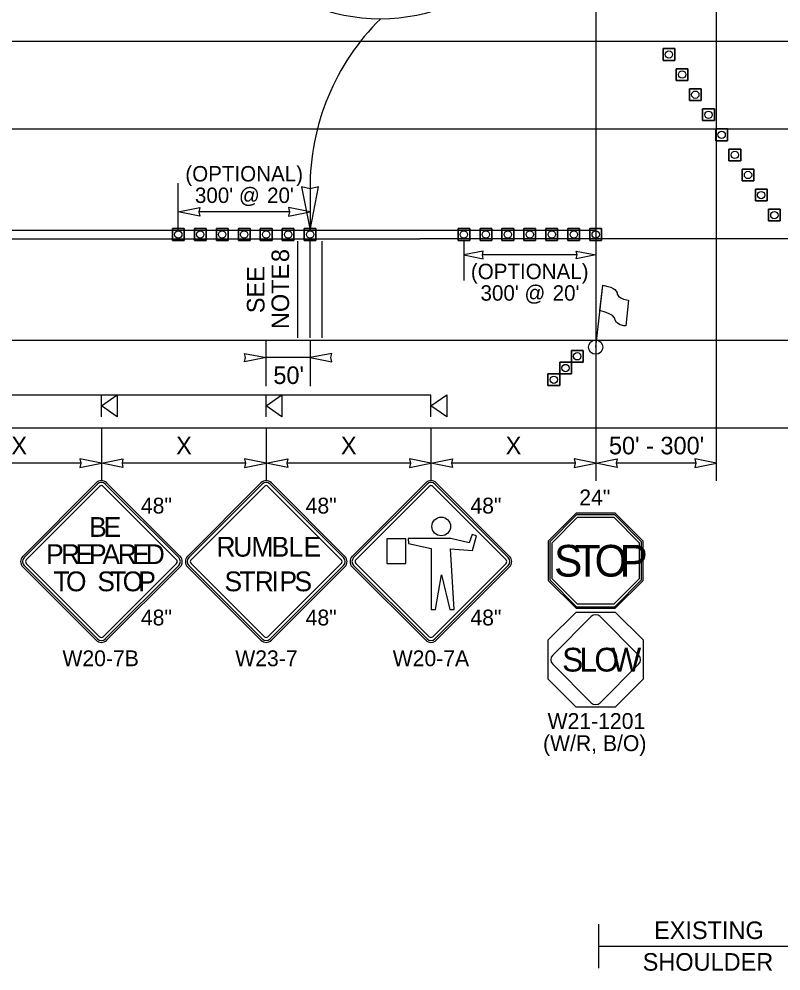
# Model space of a CAD drawing. Extents: x 99999.1 to 100095.7, y 99995 to 100010.7.
# Drawn here: x 100001.652 to 100005.12, y 100003.262 to 100007.592 of the extents above; entities that cross this region are included whole.
import ezdxf

# ---------------------------------------------------------------- set-up
doc = ezdxf.new("R2010")
doc.units = 0
for name, color, linetype in [('RD_ED_ShoulderPavedEdge', 7, 'Continuous'), ('RD_MK_LineDblYellowCenter', 7, 'Continuous'), ('RD_MK_LineEdgeWhite', 7, 'Continuous'), ('RD_MK_LineNoPass', 7, 'Continuous'), ('RD_MK_LineSkipCenter', 7, 'Continuous'), ('TR_SN_ConstructionSigns', 7, 'Continuous'), ('TR_WZ_FlaggingStation', 7, 'Continuous'), ('TR_WZ_PortableSignMountBlk-Org', 7, 'Continuous'), ('TR_WZ_TrafficCone', 7, 'Continuous'), ('TR_WZ_WorkZoneDetails', 7, 'Continuous'), ('TR_WZ_WorkZoneTextCurrent', 7, 'Continuous')]:
    doc.layers.add(name, color=color, linetype=linetype)

msp = doc.modelspace()

# ---------------------------------------------------------------- linework, layer by layer
at = {"layer": 'RD_ED_ShoulderPavedEdge'}
for p, q in [((100000.1076, 100007.4923), (100015.6424, 100007.4923)), ((100000.1076, 100005.7323), (100015.6424, 100005.7323))]:
    msp.add_line(p, q, dxfattribs=at)
at = {"layer": 'RD_MK_LineDblYellowCenter'}
for p, q in [((100000.1282, 100006.6323), (100003.4767, 100006.6323)), ((100000.0869, 100006.5923), (100003.4767, 100006.5923))]:
    msp.add_line(p, q, dxfattribs=at)
at = {"layer": 'RD_MK_LineEdgeWhite'}
for p, q in [((100000.1076, 100007.0923), (100015.6424, 100007.0923)), ((100000.1076, 100006.1323), (100015.6424, 100006.1323))]:
    msp.add_line(p, q, dxfattribs=at)
at = {"layer": 'RD_MK_LineNoPass'}
msp.add_line((100003.4767, 100006.6323), (100004.2767, 100006.6323), dxfattribs=at)
at = {"layer": 'RD_MK_LineSkipCenter'}
msp.add_lwpolyline([(100011.15, 100006.5923), (100003.4767, 100006.5923)], dxfattribs=at)
at = {"layer": 'TR_SN_ConstructionSigns'}
for p, q in [((100002.0028, 100005.4824), (100001.6687, 100005.1483)), ((100002.0088, 100005.4765), (100001.6746, 100005.1424)), ((100002.3787, 100005.1424), (100002.0445, 100005.4765)), ((100002.3846, 100005.1483), (100002.0505, 100005.4824)), ((100002.7528, 100005.4824), (100002.4187, 100005.1483)), ((100002.7588, 100005.4765), (100002.4246, 100005.1424)), ((100003.1287, 100005.1424), (100002.7945, 100005.4765)), ((100003.1346, 100005.1483), (100002.8005, 100005.4824)), ((100003.5028, 100005.4824), (100003.1687, 100005.1483)), ((100003.5088, 100005.4765), (100003.1746, 100005.1424)), ((100003.8787, 100005.1424), (100003.5445, 100005.4765)), ((100003.8846, 100005.1483), (100003.5505, 100005.4824)), ((100001.6846, 100005.1324), (100002.0187, 100005.4665)), ((100002.0346, 100005.4665), (100002.3687, 100005.1324)), ((100002.4346, 100005.1324), (100002.7687, 100005.4665)), ((100002.7846, 100005.4665), (100003.1187, 100005.1324)), ((100003.1846, 100005.1324), (100003.5187, 100005.4665)), ((100003.5346, 100005.4665), (100003.8687, 100005.1324)), ((100004.1871, 100005.3443), (100004.0606, 100005.2178)), ((100004.366, 100005.3443), (100004.1871, 100005.3443)), ((100004.4926, 100005.2178), (100004.366, 100005.3443)), ((100004.1899, 100005.3376), (100004.0673, 100005.215)), ((100004.0786, 100005.2104), (100004.1945, 100005.3263)), ((100004.3632, 100005.3376), (100004.1899, 100005.3376)), ((100004.1945, 100005.3263), (100004.3586, 100005.3263)), ((100004.3586, 100005.3263), (100004.4746, 100005.2104)), ((100004.4858, 100005.215), (100004.3632, 100005.3376)), ((100004.0606, 100005.2178), (100004.0606, 100005.0389)), ((100004.0673, 100005.215), (100004.0673, 100005.0417)), ((100004.4858, 100005.0417), (100004.4858, 100005.215)), ((100004.4926, 100005.0389), (100004.4926, 100005.2178)), ((100004.0786, 100005.0463), (100004.0786, 100005.2104)), ((100004.4746, 100005.2104), (100004.4746, 100005.0463)), ((100001.6687, 100005.1006), (100002.0028, 100004.7665)), ((100001.6746, 100005.1066), (100002.0088, 100004.7725)), ((100002.0187, 100004.7824), (100001.6846, 100005.1165)), ((100002.3687, 100005.1165), (100002.0346, 100004.7824)), ((100002.0445, 100004.7725), (100002.3787, 100005.1066)), ((100002.0505, 100004.7665), (100002.3846, 100005.1006)), ((100002.4187, 100005.1006), (100002.7528, 100004.7665)), ((100002.4246, 100005.1066), (100002.7588, 100004.7725)), ((100002.7687, 100004.7824), (100002.4346, 100005.1165)), ((100003.1187, 100005.1165), (100002.7846, 100004.7824)), ((100002.7945, 100004.7725), (100003.1287, 100005.1066)), ((100002.8005, 100004.7665), (100003.1346, 100005.1006)), ((100003.1687, 100005.1006), (100003.5028, 100004.7665)), ((100003.1746, 100005.1066), (100003.5088, 100004.7725)), ((100003.5187, 100004.7824), (100003.1846, 100005.1165)), ((100003.8687, 100005.1165), (100003.5346, 100004.7824)), ((100003.5445, 100004.7725), (100003.8787, 100005.1066)), ((100003.5505, 100004.7665), (100003.8846, 100005.1006)), ((100004.0673, 100005.0417), (100004.1899, 100004.9191)), ((100004.1945, 100004.9303), (100004.0786, 100005.0463)), ((100004.4746, 100005.0463), (100004.3586, 100004.9303)), ((100004.3632, 100004.9191), (100004.4858, 100005.0417)), ((100004.0606, 100005.0389), (100004.1871, 100004.9123)), ((100004.366, 100004.9123), (100004.4926, 100005.0389)), ((100004.1871, 100004.9123), (100004.366, 100004.9123)), ((100004.1899, 100004.9191), (100004.3632, 100004.9191)), ((100004.3586, 100004.9303), (100004.1945, 100004.9303)), ((100004.2562, 100004.874), (100004.0809, 100004.6987)), ((100004.4722, 100004.6987), (100004.2969, 100004.874)), ((100004.0809, 100004.658), (100004.2562, 100004.4827)), ((100004.2969, 100004.4827), (100004.4722, 100004.658))]:
    msp.add_line(p, q, dxfattribs=at)
for points in [[(100003.3254, 100005.2286), (100003.3254, 100005.1164), (100003.413, 100005.1164), (100003.413, 100005.2286)], [(100003.4233, 100005.2289), (100003.4246, 100005.2072), (100003.5272, 100005.1833), (100003.5272, 100004.907), (100003.5472, 100004.907), (100003.5753, 100005.064), (100003.6128, 100004.907), (100003.6319, 100004.907), (100003.6152, 100005.1832), (100003.7155, 100005.1751), (100003.7344, 100005.2421), (100003.7137, 100005.248), (100003.7005, 100005.2097), (100003.6176, 100005.2289)], [(100004.4926, 100004.7678), (100004.4926, 100004.5889), (100004.366, 100004.4623), (100004.1871, 100004.4623), (100004.0606, 100004.5889), (100004.0606, 100004.7678), (100004.1871, 100004.8943), (100004.366, 100004.8943)]]:
    msp.add_lwpolyline(points, close=True, dxfattribs=at)
msp.add_circle((100003.5736, 100005.2844), 0.0424, dxfattribs=at)
for centre, radius, start, end in [((100002.0267, 100005.4586), 0.0338, 45, 135), ((100002.0267, 100005.4586), 0.0253, 45, 135), ((100002.7767, 100005.4586), 0.0338, 45, 135), ((100002.7767, 100005.4586), 0.0253, 45, 135), ((100003.5267, 100005.4586), 0.0338, 45, 135), ((100003.5267, 100005.4586), 0.0253, 45, 135), ((100002.0267, 100005.4586), 0.0113, 45, 135), ((100002.7767, 100005.4586), 0.0113, 45, 135), ((100003.5267, 100005.4586), 0.0113, 45, 135), ((100001.6925, 100005.1245), 0.0338, 135, 225), ((100001.6925, 100005.1245), 0.0253, 135, 225), ((100001.6925, 100005.1245), 0.0113, 135, 225), ((100002.3608, 100005.1245), 0.0113, 315, 45), ((100002.3608, 100005.1245), 0.0253, 315, 45), ((100002.3608, 100005.1245), 0.0338, 315, 45), ((100002.4425, 100005.1245), 0.0338, 135, 225), ((100002.4425, 100005.1245), 0.0253, 135, 225), ((100002.4425, 100005.1245), 0.0113, 135, 225), ((100003.1108, 100005.1245), 0.0113, 315, 45), ((100003.1108, 100005.1245), 0.0253, 315, 45), ((100003.1108, 100005.1245), 0.0338, 315, 45), ((100003.1925, 100005.1245), 0.0338, 135, 225), ((100003.1925, 100005.1245), 0.0253, 135, 225), ((100003.1925, 100005.1245), 0.0113, 135, 225), ((100003.8608, 100005.1245), 0.0113, 315, 45), ((100003.8608, 100005.1245), 0.0253, 315, 45), ((100003.8608, 100005.1245), 0.0338, 315, 45), ((100004.2766, 100004.8536), 0.0288, 45, 135), ((100002.0267, 100004.7904), 0.0113, 225, 315), ((100002.7767, 100004.7904), 0.0113, 225, 315), ((100003.5267, 100004.7904), 0.0113, 225, 315), ((100002.0267, 100004.7904), 0.0338, 225, 315), ((100002.0267, 100004.7904), 0.0253, 225, 315), ((100002.7767, 100004.7904), 0.0338, 225, 315), ((100002.7767, 100004.7904), 0.0253, 225, 315), ((100003.5267, 100004.7904), 0.0338, 225, 315), ((100003.5267, 100004.7904), 0.0253, 225, 315), ((100004.1013, 100004.6783), 0.0288, 135, 225), ((100004.4518, 100004.6783), 0.0288, 315, 45), ((100004.2766, 100004.5031), 0.0288, 225, 315)]:
    msp.add_arc(centre, radius, start, end, dxfattribs=at)
at = {"layer": 'TR_WZ_FlaggingStation'}
for p, q in [((100004.2767, 100006.0998), (100004.3087, 100006.3808)), ((100004.2957, 100006.2667), (100004.3087, 100006.3811)), ((100004.4267, 100006.3133), (100004.4134, 100006.1961)), ((100004.2957, 100006.2667), (100004.2957, 100006.2667))]:
    msp.add_line(p, q, dxfattribs=at)
for points in [[(100004.3087, 100006.3811), (100004.3145, 100006.3798), (100004.3323, 100006.3764), (100004.3461, 100006.3722), (100004.3558, 100006.3661), (100004.3643, 100006.3614), (100004.37, 100006.3546), (100004.3743, 100006.3467), (100004.3748, 100006.3405), (100004.3802, 100006.3313), (100004.391, 100006.3239), (100004.4034, 100006.3187), (100004.4267, 100006.3133)], [(100004.4134, 100006.1961), (100004.4052, 100006.1975), (100004.3876, 100006.2021), (100004.3719, 100006.2126), (100004.3654, 100006.2232), (100004.3615, 100006.2335), (100004.3524, 100006.2444), (100004.3414, 100006.2506), (100004.3241, 100006.2577), (100004.2957, 100006.2667)]]:
    msp.add_lwpolyline(points, dxfattribs=at)
msp.add_circle((100004.2767, 100006.0998), 0.0325, dxfattribs=at)
at = {"layer": 'TR_WZ_PortableSignMountBlk-Org'}
for p, q in [((100002.0267, 100005.7824), (100002.0267, 100005.8824)), ((100002.7767, 100005.7824), (100002.7767, 100005.8824)), ((100003.5267, 100005.7824), (100003.5267, 100005.8824))]:
    msp.add_line(p, q, dxfattribs=at)
for points in [[(100002.0267, 100005.8323), (100002.0985, 100005.8824), (100002.0985, 100005.7824)], [(100002.7767, 100005.8323), (100002.8485, 100005.8824), (100002.8485, 100005.7824)], [(100003.5267, 100005.8323), (100003.5985, 100005.8824), (100003.5985, 100005.7824)]]:
    msp.add_lwpolyline(points, close=True, dxfattribs=at)
at = {"layer": 'TR_WZ_TrafficCone'}
for points in [[(100004.6367, 100007.4577), (100004.5834, 100007.4577), (100004.5834, 100007.4043), (100004.6367, 100007.4043), (100004.6367, 100007.4577)], [(100004.6367, 100007.4043), (100004.5834, 100007.4043), (100004.5834, 100007.4577), (100004.6367, 100007.4577), (100004.6367, 100007.4043)], [(100004.6967, 100007.3663), (100004.6434, 100007.3663), (100004.6434, 100007.313), (100004.6967, 100007.313), (100004.6967, 100007.3663)], [(100004.6967, 100007.313), (100004.6434, 100007.313), (100004.6434, 100007.3663), (100004.6967, 100007.3663), (100004.6967, 100007.313)], [(100004.7567, 100007.275), (100004.7034, 100007.275), (100004.7034, 100007.2217), (100004.7567, 100007.2217), (100004.7567, 100007.275)], [(100004.7567, 100007.2217), (100004.7034, 100007.2217), (100004.7034, 100007.275), (100004.7567, 100007.275), (100004.7567, 100007.2217)], [(100004.8167, 100007.1837), (100004.7634, 100007.1837), (100004.7634, 100007.1303), (100004.8167, 100007.1303), (100004.8167, 100007.1837)], [(100004.8167, 100007.1303), (100004.7634, 100007.1303), (100004.7634, 100007.1837), (100004.8167, 100007.1837), (100004.8167, 100007.1303)], [(100004.8234, 100007.0923), (100004.8767, 100007.0923), (100004.8767, 100007.039), (100004.8234, 100007.039), (100004.8234, 100007.0923)], [(100004.8234, 100007.039), (100004.8767, 100007.039), (100004.8767, 100007.0923), (100004.8234, 100007.0923), (100004.8234, 100007.039)], [(100004.8834, 100007.001), (100004.9367, 100007.001), (100004.9367, 100006.9477), (100004.8834, 100006.9477), (100004.8834, 100007.001)], [(100004.8834, 100006.9477), (100004.9367, 100006.9477), (100004.9367, 100007.001), (100004.8834, 100007.001), (100004.8834, 100006.9477)], [(100004.9434, 100006.9097), (100004.9967, 100006.9097), (100004.9967, 100006.8563), (100004.9434, 100006.8563), (100004.9434, 100006.9097)], [(100004.9434, 100006.8563), (100004.9967, 100006.8563), (100004.9967, 100006.9097), (100004.9434, 100006.9097), (100004.9434, 100006.8563)], [(100005.0034, 100006.8183), (100005.0567, 100006.8183), (100005.0567, 100006.765), (100005.0034, 100006.765), (100005.0034, 100006.8183)], [(100005.0034, 100006.765), (100005.0567, 100006.765), (100005.0567, 100006.8183), (100005.0034, 100006.8183), (100005.0034, 100006.765)], [(100005.0634, 100006.727), (100005.1167, 100006.727), (100005.1167, 100006.6737), (100005.0634, 100006.6737), (100005.0634, 100006.727)], [(100005.0634, 100006.6737), (100005.1167, 100006.6737), (100005.1167, 100006.727), (100005.0634, 100006.727), (100005.0634, 100006.6737)], [(100002.4033, 100006.639), (100002.35, 100006.639), (100002.35, 100006.5857), (100002.4033, 100006.5857), (100002.4033, 100006.639)], [(100002.4033, 100006.5857), (100002.35, 100006.5857), (100002.35, 100006.639), (100002.4033, 100006.639), (100002.4033, 100006.5857)], [(100002.5033, 100006.639), (100002.45, 100006.639), (100002.45, 100006.5857), (100002.5033, 100006.5857), (100002.5033, 100006.639)], [(100002.5033, 100006.5857), (100002.45, 100006.5857), (100002.45, 100006.639), (100002.5033, 100006.639), (100002.5033, 100006.5857)], [(100002.6033, 100006.639), (100002.55, 100006.639), (100002.55, 100006.5857), (100002.6033, 100006.5857), (100002.6033, 100006.639)], [(100002.6033, 100006.5857), (100002.55, 100006.5857), (100002.55, 100006.639), (100002.6033, 100006.639), (100002.6033, 100006.5857)], [(100002.7033, 100006.639), (100002.65, 100006.639), (100002.65, 100006.5857), (100002.7033, 100006.5857), (100002.7033, 100006.639)], [(100002.7033, 100006.5857), (100002.65, 100006.5857), (100002.65, 100006.639), (100002.7033, 100006.639), (100002.7033, 100006.5857)], [(100002.8033, 100006.639), (100002.75, 100006.639), (100002.75, 100006.5857), (100002.8033, 100006.5857), (100002.8033, 100006.639)], [(100002.8033, 100006.5857), (100002.75, 100006.5857), (100002.75, 100006.639), (100002.8033, 100006.639), (100002.8033, 100006.5857)], [(100002.9033, 100006.639), (100002.85, 100006.639), (100002.85, 100006.5857), (100002.9033, 100006.5857), (100002.9033, 100006.639)], [(100002.9033, 100006.5857), (100002.85, 100006.5857), (100002.85, 100006.639), (100002.9033, 100006.639), (100002.9033, 100006.5857)], [(100003.0033, 100006.639), (100002.95, 100006.639), (100002.95, 100006.5857), (100003.0033, 100006.5857), (100003.0033, 100006.639)], [(100003.0033, 100006.5857), (100002.95, 100006.5857), (100002.95, 100006.639), (100003.0033, 100006.639), (100003.0033, 100006.5857)], [(100003.7033, 100006.639), (100003.65, 100006.639), (100003.65, 100006.5857), (100003.7033, 100006.5857), (100003.7033, 100006.639)], [(100003.7033, 100006.5857), (100003.65, 100006.5857), (100003.65, 100006.639), (100003.7033, 100006.639), (100003.7033, 100006.5857)], [(100003.8033, 100006.639), (100003.75, 100006.639), (100003.75, 100006.5857), (100003.8033, 100006.5857), (100003.8033, 100006.639)], [(100003.8033, 100006.5857), (100003.75, 100006.5857), (100003.75, 100006.639), (100003.8033, 100006.639), (100003.8033, 100006.5857)], [(100003.9033, 100006.639), (100003.85, 100006.639), (100003.85, 100006.5857), (100003.9033, 100006.5857), (100003.9033, 100006.639)], [(100003.9033, 100006.5857), (100003.85, 100006.5857), (100003.85, 100006.639), (100003.9033, 100006.639), (100003.9033, 100006.5857)], [(100004.0033, 100006.639), (100003.95, 100006.639), (100003.95, 100006.5857), (100004.0033, 100006.5857), (100004.0033, 100006.639)], [(100004.0033, 100006.5857), (100003.95, 100006.5857), (100003.95, 100006.639), (100004.0033, 100006.639), (100004.0033, 100006.5857)], [(100004.1033, 100006.639), (100004.05, 100006.639), (100004.05, 100006.5857), (100004.1033, 100006.5857), (100004.1033, 100006.639)], [(100004.1033, 100006.5857), (100004.05, 100006.5857), (100004.05, 100006.639), (100004.1033, 100006.639), (100004.1033, 100006.5857)], [(100004.2033, 100006.639), (100004.15, 100006.639), (100004.15, 100006.5857), (100004.2033, 100006.5857), (100004.2033, 100006.639)], [(100004.2033, 100006.5857), (100004.15, 100006.5857), (100004.15, 100006.639), (100004.2033, 100006.639), (100004.2033, 100006.5857)], [(100004.3033, 100006.639), (100004.25, 100006.639), (100004.25, 100006.5857), (100004.3033, 100006.5857), (100004.3033, 100006.639)], [(100004.3033, 100006.5857), (100004.25, 100006.5857), (100004.25, 100006.639), (100004.3033, 100006.639), (100004.3033, 100006.5857)], [(100004.166, 100006.085), (100004.2193, 100006.085), (100004.2193, 100006.0317), (100004.166, 100006.0317), (100004.166, 100006.085)], [(100004.166, 100006.0317), (100004.2193, 100006.0317), (100004.2193, 100006.085), (100004.166, 100006.085), (100004.166, 100006.0317)], [(100004.1127, 100006.0317), (100004.166, 100006.0317), (100004.166, 100005.9783), (100004.1127, 100005.9783), (100004.1127, 100006.0317)], [(100004.1127, 100005.9783), (100004.166, 100005.9783), (100004.166, 100006.0317), (100004.1127, 100006.0317), (100004.1127, 100005.9783)], [(100004.0593, 100005.9783), (100004.1127, 100005.9783), (100004.1127, 100005.925), (100004.0593, 100005.925), (100004.0593, 100005.9783)], [(100004.0593, 100005.925), (100004.1127, 100005.925), (100004.1127, 100005.9783), (100004.0593, 100005.9783), (100004.0593, 100005.925)]]:
    msp.add_lwpolyline(points, dxfattribs=at)
for centre in [(100004.61, 100007.431), (100004.67, 100007.3397), (100004.73, 100007.2483), (100004.79, 100007.157), (100004.85, 100007.0657), (100004.91, 100006.9743), (100004.97, 100006.883), (100005.03, 100006.7917), (100005.09, 100006.7003), (100002.3767, 100006.6123), (100002.4767, 100006.6123), (100002.5767, 100006.6123), (100002.6767, 100006.6123), (100002.7767, 100006.6123), (100002.8767, 100006.6123), (100002.9767, 100006.6123), (100003.6767, 100006.6123), (100003.7767, 100006.6123), (100003.8767, 100006.6123), (100003.9767, 100006.6123), (100004.0767, 100006.6123), (100004.1767, 100006.6123), (100004.2767, 100006.6123), (100004.1927, 100006.0583), (100004.1393, 100006.005), (100004.086, 100005.9517)]:
    msp.add_circle(centre, 0.0167, dxfattribs=at)
at = {"layer": 'TR_WZ_WorkZoneDetails'}
for p, q in [((100004.2767, 100008.9491), (100004.2767, 100005.4923)), ((100004.8267, 100005.4923), (100004.8267, 100007.7323)), ((100002.3767, 100006.6357), (100002.3767, 100006.8457)), ((100002.9767, 100006.8457), (100002.9767, 100006.6357)), ((100002.8829, 100006.7157), (100002.4704, 100006.7157)), ((100002.921, 100006.1423), (100002.921, 100006.5823)), ((100002.9767, 100006.1423), (100002.9767, 100006.5823)), ((100003.0315, 100006.1423), (100003.0315, 100006.5823)), ((100003.6767, 100006.5857), (100003.6767, 100006.4023)), ((100004.1923, 100006.5193), (100003.761, 100006.5193)), ((100002.7767, 100005.9223), (100002.7767, 100006.1323)), ((100002.9767, 100006.1323), (100002.9767, 100005.9223)), ((100002.9767, 100006.0523), (100002.7767, 100006.0523)), ((100000.5267, 100005.8824), (100003.5267, 100005.8824)), ((100002.0267, 100005.7323), (100002.0267, 100005.4923)), ((100002.7767, 100005.7323), (100002.7767, 100005.4923)), ((100003.5267, 100005.7323), (100003.5267, 100005.4923)), ((100001.9329, 100005.5723), (100001.3704, 100005.5723)), ((100002.6829, 100005.5723), (100002.1204, 100005.5723)), ((100003.4329, 100005.5723), (100002.8704, 100005.5723)), ((100004.1829, 100005.5723), (100003.6204, 100005.5723)), ((100004.7329, 100005.5723), (100004.3704, 100005.5723)), ((100004.2907, 100003.2755), (100004.2907, 100003.4755)), ((100004.2907, 100003.3755), (100005.2907, 100003.3755))]:
    msp.add_line(p, q, dxfattribs=at)
for points in [[(100002.9767, 100006.6323), (100003.0152, 100006.8289), (100002.9767, 100006.8198), (100002.9381, 100006.8289)], [(100002.3767, 100006.7157), (100002.4749, 100006.7349), (100002.4704, 100006.7157), (100002.4749, 100006.6964)], [(100002.9767, 100006.7157), (100002.8784, 100006.7349), (100002.8829, 100006.7157), (100002.8784, 100006.6964)], [(100003.6767, 100006.5193), (100003.7651, 100006.502), (100003.761, 100006.5193), (100003.7651, 100006.5367)], [(100004.2767, 100006.5193), (100004.1882, 100006.502), (100004.1923, 100006.5193), (100004.1882, 100006.5367)], [(100002.7767, 100006.0523), (100002.6784, 100006.0331), (100002.6829, 100006.0523), (100002.6784, 100006.0716)], [(100002.9767, 100006.0523), (100003.0749, 100006.0331), (100003.0704, 100006.0523), (100003.0749, 100006.0716)], [(100002.0267, 100005.5723), (100001.9284, 100005.5916), (100001.9329, 100005.5723), (100001.9284, 100005.5531)], [(100002.0267, 100005.5723), (100002.1249, 100005.5916), (100002.1204, 100005.5723), (100002.1249, 100005.5531)], [(100002.7767, 100005.5723), (100002.6784, 100005.5916), (100002.6829, 100005.5723), (100002.6784, 100005.5531)], [(100002.7767, 100005.5723), (100002.8749, 100005.5916), (100002.8704, 100005.5723), (100002.8749, 100005.5531)], [(100003.5267, 100005.5723), (100003.4284, 100005.5916), (100003.4329, 100005.5723), (100003.4284, 100005.5531)], [(100003.5267, 100005.5723), (100003.6249, 100005.5916), (100003.6204, 100005.5723), (100003.6249, 100005.5531)], [(100004.2767, 100005.5723), (100004.1784, 100005.5916), (100004.1829, 100005.5723), (100004.1784, 100005.5531)], [(100004.2767, 100005.5723), (100004.3749, 100005.5916), (100004.3704, 100005.5723), (100004.3749, 100005.5531)], [(100004.8267, 100005.5723), (100004.7284, 100005.5916), (100004.7329, 100005.5723), (100004.7284, 100005.5531)]]:
    msp.add_lwpolyline(points, close=True, dxfattribs=at)
msp.add_circle((100003.2965, 100008.4168), 0.8245, dxfattribs=at)
msp.add_arc((100004.0525, 100006.8268), 1.0759, 134.6391, 180.3733, dxfattribs=at)

# ---------------------------------------------------------------- texts
at = {"layer": 'TR_SN_ConstructionSigns'}
for s, height, p in [('24"', 0.072, (100004.2019, 100005.3803)), ('B', 0.09, (100001.9709, 100005.237)), ('E', 0.09, (100002.0366, 100005.237)), ('R', 0.09, (100002.5503, 100005.147)), ('U', 0.09, (100002.6268, 100005.147)), ('M', 0.09, (100002.7096, 100005.147)), ('B', 0.09, (100002.8014, 100005.147)), ('L', 0.09, (100002.8779, 100005.147)), ('E', 0.09, (100002.9472, 100005.147)), ('P', 0.09, (100001.7747, 100005.1132)), ('R', 0.09, (100001.8431, 100005.1132)), ('E', 0.09, (100001.9088, 100005.1132)), ('P', 0.09, (100001.97, 100005.1132)), ('A', 0.09, (100002.0312, 100005.1132)), ('R', 0.09, (100002.1014, 100005.1132)), ('E', 0.09, (100002.1671, 100005.1132)), ('D', 0.09, (100002.2283, 100005.1132)), ('S', 0.144, (100004.0872, 100005.0563)), ('T', 0.144, (100004.1808, 100005.0563)), ('O', 0.144, (100004.2715, 100005.0563)), ('P', 0.144, (100004.3853, 100005.0563)), ('T', 0.09, (100001.8084, 100004.9895)), ('O', 0.09, (100001.8651, 100004.9895)), ('S', 0.09, (100002.0082, 100004.9895)), ('T', 0.09, (100002.0667, 100004.9895)), ('O', 0.09, (100002.1234, 100004.9895)), ('P', 0.09, (100002.1945, 100004.9895)), ('S', 0.09, (100002.5868, 100004.9895)), ('T', 0.09, (100002.6552, 100004.9895)), ('R', 0.09, (100002.7245, 100004.9895)), ('I', 0.09, (100002.801, 100004.9895)), ('P', 0.09, (100002.837, 100004.9895)), ('S', 0.09, (100002.9054, 100004.9895)), ('S', 0.108, (100004.1238, 100004.6243)), ('L', 0.108, (100004.2026, 100004.6243)), ('O', 0.108, (100004.2706, 100004.6243)), ('W', 0.108, (100004.3473, 100004.6243))]:
    msp.add_text(s, height=height, dxfattribs=at).set_placement(p)
for s, p in [('48"', (100002.2064, 100005.343)), ('48"', (100002.9564, 100005.343)), ('48"', (100003.7064, 100005.343)), ('48"', (100002.2064, 100004.8339)), ('48"', (100002.9564, 100004.8339)), ('48"', (100003.7064, 100004.8339)), ('W20-7B', (100001.8493, 100004.6486)), ('W23-7', (100002.6361, 100004.6486)), ('W20-7A', (100003.3527, 100004.6486)), ('W21-1201', (100004.0578, 100004.3633)), ('(W/R, B/O)', (100004.0369, 100004.2625))]:
    msp.add_text(s, height=0.072, rotation=360, dxfattribs=at).set_placement(p)
at = {"layer": 'TR_WZ_WorkZoneDetails'}
for s, rotation, p in [('8', 90, (100002.881, 100006.4868)), ('NOTE', 90, (100002.881, 100006.182)), ('SEE', 90, (100002.769, 100006.2544)), ('EXISTING', 360, (100004.5424, 100003.4075)), ('SHOULDER', 360, (100004.4905, 100003.2635))]:
    msp.add_text(s, height=0.08, rotation=rotation, dxfattribs=at).set_placement(p)
at = {"layer": 'TR_WZ_WorkZoneTextCurrent'}
for s, height, p in [('(OPTIONAL)', 0.07, (100002.4087, 100006.8537)), ("300' @", 0.07, (100002.4524, 100006.7557)), ("20'", 0.07, (100002.7808, 100006.7557)), ('(OPTIONAL)', 0.07, (100003.7085, 100006.4093)), ("300' @", 0.07, (100003.7523, 100006.3113)), ("20'", 0.07, (100004.0807, 100006.3113)), ("50'", 0.08, (100002.8094, 100005.9323))]:
    msp.add_text(s, height=height, dxfattribs=at).set_placement(p)
for s, p in [('X', (100001.6169, 100005.6123)), ('X', (100002.3669, 100005.6123)), ('X', (100003.1169, 100005.6123)), ('X', (100003.8669, 100005.6123)), ("50' - 300'", (100004.3369, 100005.6123))]:
    msp.add_text(s, height=0.08, rotation=360, dxfattribs=at).set_placement(p)

doc.saveas('drawing.dxf')
